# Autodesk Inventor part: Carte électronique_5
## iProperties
Created: 2010-07
Part Number: Carte électronique_5
Document SubType Name: Modeling
Designer: eric
Density: 1 g/cm^3
Author: eric
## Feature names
1. Base1
